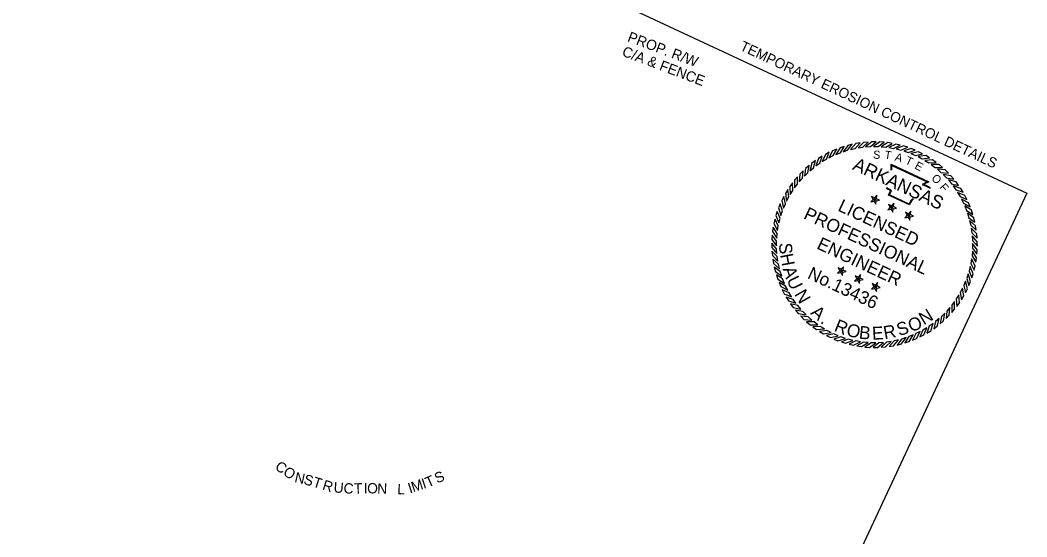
# Model space of a CAD drawing. Extents: x 980231 to 982096, y 1837566 to 1839185.
# Drawn here: x 981512 to 982096, y 1838266 to 1838566 of the extents above; entities that cross this region are included whole.
import ezdxf

# ---------------------------------------------------------------- set-up
doc = ezdxf.new("R2010")
doc.units = 0
for name, color, linetype in [('1', 7, 'Continuous'), ('G-ANNO-SYMB', 7, 'Continuous'), ('G-Border-Sheet', 7, 'Continuous'), ('R_Draft', 7, 'Continuous')]:
    doc.layers.add(name, color=color, linetype=linetype)

msp = doc.modelspace()

# ---------------------------------------------------------------- linework, layer by layer
at = {"layer": 'G-ANNO-SYMB'}
for points in [[(981994.88, 1838494.09), (981992.39, 1838493.47), (981989.67, 1838489.8), (981992.31, 1838490.62)], [(981999.49, 1838494.93), (981996.96, 1838494.51), (981993.96, 1838491.06), (981996.66, 1838491.68)], [(982004.15, 1838495.41), (982001.59, 1838495.19), (981998.33, 1838491.99), (982001.07, 1838492.39)], [(982008.83, 1838495.53), (982006.26, 1838495.51), (982002.76, 1838492.57), (982005.53, 1838492.75)], [(982013.51, 1838495.27), (982010.95, 1838495.46), (982007.23, 1838492.8), (982010, 1838492.77)], [(982018.15, 1838494.65), (982015.61, 1838495.04), (982011.69, 1838492.68), (982014.45, 1838492.43)], [(982022.73, 1838493.67), (982020.23, 1838494.25), (982016.14, 1838492.21), (982018.87, 1838491.74)], [(981981.65, 1838489.43), (981979.37, 1838488.25), (981977.58, 1838484.04), (981979.97, 1838485.46)], [(981985.93, 1838491.33), (981983.57, 1838490.33), (981981.46, 1838486.27), (981983.94, 1838487.5)], [(981990.35, 1838492.88), (981987.92, 1838492.07), (981985.49, 1838488.2), (981988.07, 1838489.23)], [(982027.22, 1838492.33), (982024.77, 1838493.11), (982020.53, 1838491.39), (982023.22, 1838490.71)], [(982031.59, 1838490.64), (982029.21, 1838491.61), (982024.85, 1838490.23), (982027.48, 1838489.34)], [(982035.81, 1838488.62), (982033.52, 1838489.77), (982029.06, 1838488.74), (982031.61, 1838487.65)], [(981973.59, 1838484.66), (981971.53, 1838483.14), (981970.42, 1838478.7), (981972.55, 1838480.48)], [(981977.53, 1838487.2), (981975.35, 1838485.85), (981973.9, 1838481.51), (981976.16, 1838483.12)], [(982039.87, 1838486.27), (982037.67, 1838487.59), (982033.15, 1838486.92), (982035.6, 1838485.63)], [(982043.72, 1838483.6), (982041.64, 1838485.1), (982037.07, 1838484.78), (982039.42, 1838483.3)], [(982047.36, 1838480.65), (982045.39, 1838482.3), (982040.82, 1838482.34), (982043.04, 1838480.69)], [(981966.39, 1838478.69), (981964.58, 1838476.86), (981964.18, 1838472.31), (981966.01, 1838474.39)], [(981969.87, 1838481.82), (981967.93, 1838480.14), (981967.18, 1838475.63), (981969.16, 1838477.56)], [(982050.75, 1838477.42), (982048.92, 1838479.22), (982044.37, 1838479.62), (982046.45, 1838477.79)], [(982053.87, 1838473.93), (982052.2, 1838475.87), (982047.69, 1838476.63), (982049.62, 1838474.64)], [(981960.2, 1838471.66), (981958.7, 1838469.58), (981959.02, 1838465.01), (981960.5, 1838467.36)], [(981963.15, 1838475.3), (981961.5, 1838473.33), (981961.46, 1838468.76), (981963.12, 1838470.99)], [(982056.72, 1838470.21), (982055.2, 1838472.27), (982050.76, 1838473.38), (982052.54, 1838471.25)], [(981957.54, 1838467.81), (981956.21, 1838465.61), (981956.89, 1838461.09), (981958.18, 1838463.54)], [(982008.08, 1838462.01), (982009, 1838462.52), (982009.24, 1838464.49), (982007.89, 1838463.04)], [(982059.26, 1838466.28), (982057.91, 1838468.45), (982053.57, 1838469.91), (982055.17, 1838467.64)], [(982061.49, 1838462.15), (982060.31, 1838464.43), (982056.1, 1838466.22), (982057.52, 1838463.84)], [(981953.16, 1838459.53), (981952.2, 1838457.15), (981953.57, 1838452.79), (981954.46, 1838455.42)], [(981955.19, 1838463.75), (981954.04, 1838461.46), (981955.07, 1838457.01), (981956.16, 1838459.55)], [(982008.08, 1838462.01), (982007.05, 1838462.14), (982005.7, 1838460.69), (982007.64, 1838461.07)], [(982008.08, 1838462.01), (982007.89, 1838463.04), (982006.09, 1838463.87), (982007.05, 1838462.14)], [(982008.08, 1838462.01), (982007.64, 1838461.07), (982008.6, 1838459.34), (982008.85, 1838461.3)], [(982008.08, 1838462.01), (982008.85, 1838461.3), (982010.79, 1838461.68), (982009, 1838462.52)], [(982017.97, 1838457.4), (982017.77, 1838458.43), (982015.98, 1838459.26), (982016.94, 1838457.53)], [(982017.97, 1838457.4), (982018.88, 1838457.91), (982019.12, 1838459.87), (982017.77, 1838458.43)], [(982063.39, 1838457.87), (982062.39, 1838460.23), (982058.33, 1838462.35), (982059.56, 1838459.86)], [(981951.48, 1838455.16), (981950.7, 1838452.71), (981952.41, 1838448.48), (981953.09, 1838451.16)], [(982017.97, 1838457.4), (982016.94, 1838457.53), (982015.59, 1838456.08), (982017.53, 1838456.46)], [(982017.97, 1838457.4), (982017.53, 1838456.46), (982018.49, 1838454.73), (982018.73, 1838456.69)], [(982017.97, 1838457.4), (982018.73, 1838456.69), (982020.68, 1838457.07), (982018.88, 1838457.91)], [(982027.86, 1838452.79), (982026.82, 1838452.92), (982025.47, 1838451.47), (982027.42, 1838451.85)], [(982027.86, 1838452.79), (982027.66, 1838453.82), (982025.86, 1838454.65), (982026.82, 1838452.92)], [(982027.86, 1838452.79), (982027.42, 1838451.85), (982028.38, 1838450.12), (982028.62, 1838452.08)], [(982027.86, 1838452.79), (982028.77, 1838453.3), (982029.01, 1838455.26), (982027.66, 1838453.82)], [(982027.86, 1838452.79), (982028.62, 1838452.08), (982030.57, 1838452.46), (982028.77, 1838453.3)], [(982064.94, 1838453.45), (982064.13, 1838455.89), (982060.26, 1838458.31), (982061.29, 1838455.74)], [(982066.15, 1838448.93), (982065.53, 1838451.42), (982061.85, 1838454.14), (982062.68, 1838451.49)], [(981950.14, 1838450.67), (981949.55, 1838448.17), (981951.59, 1838444.08), (981952.06, 1838446.81)], [(982066.99, 1838444.32), (982066.57, 1838446.85), (982063.12, 1838449.85), (982063.74, 1838447.15)], [(981948.53, 1838441.45), (981948.35, 1838438.89), (981951, 1838435.17), (981951.04, 1838437.94)], [(981949.15, 1838446.09), (981948.77, 1838443.55), (981951.12, 1838439.63), (981951.37, 1838442.4)], [(982067.47, 1838439.66), (982067.25, 1838442.21), (982064.05, 1838445.48), (982064.45, 1838442.73)], [(982067.58, 1838434.97), (982067.57, 1838437.54), (982064.63, 1838441.04), (982064.81, 1838438.28)], [(981948.28, 1838436.77), (981948.3, 1838434.2), (981951.23, 1838430.7), (981951.05, 1838433.47)], [(982067.33, 1838430.3), (982067.51, 1838432.86), (982064.86, 1838436.58), (982064.83, 1838433.81)], [(981948.39, 1838432.09), (981948.61, 1838429.53), (981951.82, 1838426.27), (981951.41, 1838429.01)], [(982066.71, 1838425.65), (982067.09, 1838428.19), (982064.74, 1838432.11), (982064.49, 1838429.35)], [(981948.87, 1838427.43), (981949.29, 1838424.9), (981952.74, 1838421.9), (981952.13, 1838424.6)], [(982065.73, 1838421.07), (982066.31, 1838423.57), (982064.27, 1838427.66), (982063.8, 1838424.93)], [(981949.72, 1838422.82), (981950.33, 1838420.33), (981954.01, 1838417.61), (981953.18, 1838420.26)], [(981950.92, 1838418.29), (981951.73, 1838415.86), (981955.61, 1838413.43), (981954.58, 1838416.01)], [(981988.78, 1838420.61), (981987.74, 1838420.74), (981986.39, 1838419.29), (981988.34, 1838419.67)], [(981988.78, 1838420.61), (981988.58, 1838421.63), (981986.78, 1838422.47), (981987.74, 1838420.74)], [(981988.78, 1838420.61), (981988.34, 1838419.67), (981989.3, 1838417.93), (981989.54, 1838419.9)], [(981988.78, 1838420.61), (981989.69, 1838421.12), (981989.93, 1838423.08), (981988.58, 1838421.63)], [(981988.78, 1838420.61), (981989.54, 1838419.9), (981991.49, 1838420.28), (981989.69, 1838421.12)], [(981998.67, 1838416), (981998.47, 1838417.02), (981996.67, 1838417.86), (981997.63, 1838416.13)], [(981998.67, 1838416), (981999.58, 1838416.51), (981999.82, 1838418.47), (981998.47, 1838417.02)], [(982062.7, 1838412.21), (982063.67, 1838414.59), (982062.29, 1838418.95), (982061.4, 1838416.33)], [(982064.39, 1838416.58), (982065.16, 1838419.03), (982063.45, 1838423.27), (982062.77, 1838420.58)], [(981952.48, 1838413.87), (981953.47, 1838411.51), (981957.53, 1838409.4), (981956.3, 1838411.88)], [(981998.67, 1838416), (981997.63, 1838416.13), (981996.28, 1838414.68), (981998.23, 1838415.06)], [(981998.67, 1838416), (981998.23, 1838415.06), (981999.19, 1838413.32), (981999.43, 1838415.29)], [(981998.67, 1838416), (981999.43, 1838415.29), (982001.37, 1838415.67), (981999.58, 1838416.51)], [(982008.55, 1838411.39), (982008.35, 1838412.41), (982006.56, 1838413.25), (982007.52, 1838411.52)], [(982008.55, 1838411.39), (982009.46, 1838411.9), (982009.7, 1838413.86), (982008.35, 1838412.41)], [(982008.55, 1838411.39), (982009.31, 1838410.68), (982011.26, 1838411.06), (982009.46, 1838411.9)], [(982060.67, 1838407.99), (982061.82, 1838410.28), (982060.8, 1838414.74), (982059.7, 1838412.19)], [(981954.37, 1838409.59), (981955.55, 1838407.31), (981959.76, 1838405.53), (981958.34, 1838407.91)], [(982008.55, 1838411.39), (982007.52, 1838411.52), (982006.17, 1838410.07), (982008.11, 1838410.45)], [(982008.55, 1838411.39), (982008.11, 1838410.45), (982009.07, 1838408.71), (982009.31, 1838410.68)], [(982055.66, 1838400.08), (982057.16, 1838402.17), (982056.84, 1838406.73), (982055.36, 1838404.38)], [(982058.32, 1838403.94), (982059.65, 1838406.13), (982058.98, 1838410.66), (982057.69, 1838408.2)], [(981956.6, 1838405.47), (981957.95, 1838403.29), (981962.29, 1838401.84), (981960.69, 1838404.1)], [(981959.14, 1838401.54), (981960.67, 1838399.47), (981965.1, 1838398.36), (981963.33, 1838400.49)], [(982052.71, 1838396.45), (982054.36, 1838398.41), (982054.4, 1838402.98), (982052.75, 1838400.76)], [(981961.99, 1838397.81), (981963.67, 1838395.87), (981968.18, 1838395.12), (981966.24, 1838397.1)], [(981965.12, 1838394.33), (981966.94, 1838392.52), (981971.5, 1838392.13), (981969.41, 1838393.95)], [(982045.99, 1838389.93), (982047.93, 1838391.61), (982048.68, 1838396.12), (982046.7, 1838394.18)], [(982049.48, 1838393.06), (982051.28, 1838394.88), (982051.68, 1838399.44), (982049.85, 1838397.35)], [(981968.51, 1838391.1), (981970.47, 1838389.44), (981975.04, 1838389.4), (981972.82, 1838391.06)], [(981972.14, 1838388.14), (981974.23, 1838386.65), (981978.79, 1838386.96), (981976.44, 1838388.44)], [(982038.33, 1838384.54), (982040.51, 1838385.9), (982041.96, 1838390.23), (982039.7, 1838388.63)], [(982042.27, 1838387.08), (982044.33, 1838388.61), (982045.44, 1838393.04), (982043.31, 1838391.27)], [(981976, 1838385.48), (981978.19, 1838384.15), (981982.72, 1838384.83), (981980.26, 1838386.12)], [(981980.05, 1838383.13), (981982.34, 1838381.98), (981986.8, 1838383.01), (981984.25, 1838384.1)], [(982025.51, 1838378.86), (982027.95, 1838379.67), (982030.37, 1838383.55), (982027.8, 1838382.52)], [(982029.93, 1838380.42), (982032.29, 1838381.41), (982034.41, 1838385.47), (982031.92, 1838384.24)], [(982034.21, 1838382.31), (982036.49, 1838383.49), (982038.28, 1838387.7), (982035.9, 1838386.28)], [(981984.27, 1838381.1), (981986.65, 1838380.14), (981991.01, 1838381.51), (981988.39, 1838382.4)], [(981988.64, 1838379.42), (981991.09, 1838378.64), (981995.33, 1838380.35), (981992.64, 1838381.03)], [(981993.13, 1838378.08), (981995.63, 1838377.49), (981999.72, 1838379.54), (981996.99, 1838380)], [(981997.71, 1838377.09), (982000.25, 1838376.71), (982004.17, 1838379.06), (982001.41, 1838379.32)], [(982002.36, 1838376.47), (982004.92, 1838376.29), (982008.64, 1838378.94), (982005.87, 1838378.98)], [(982007.03, 1838376.22), (982009.6, 1838376.24), (982013.1, 1838379.18), (982010.34, 1838378.99)], [(982011.72, 1838376.33), (982014.27, 1838376.55), (982017.53, 1838379.76), (982014.79, 1838379.36)], [(982016.38, 1838376.81), (982018.91, 1838377.23), (982021.91, 1838380.68), (982019.21, 1838380.07)], [(982020.98, 1838377.66), (982023.47, 1838378.27), (982026.19, 1838381.95), (982023.55, 1838381.12)]]:
    msp.add_lwpolyline(points, close=True, dxfattribs=at)
for points in [[(982017.57, 1838479.15), (982017.58, 1838482.47), (982039.4, 1838472.32), (982036.51, 1838470.88), (982038, 1838470.2), (982039.24, 1838469.64), (982040.42, 1838468.93)], [(982017.95, 1838479.15), (982017.96, 1838481.88), (982038.52, 1838472.3), (982035.62, 1838470.86), (982037.84, 1838469.86), (982039.06, 1838469.3), (982040.22, 1838468.61)], [(982030.42, 1838462.04), (982029.91, 1838461.91), (982029.57, 1838461.51), (982028.92, 1838460.44), (982028.22, 1838458.93), (982016.04, 1838464.61), (982016.99, 1838466.64), (982017.2, 1838467.1), (982016.78, 1838467.48), (982015.05, 1838468.28), (982014.96, 1838468.9)], [(982030.33, 1838462.41), (982029.69, 1838462.25), (982029.26, 1838461.74), (982028.58, 1838460.62), (982028.03, 1838459.44), (982016.55, 1838464.79), (982017.34, 1838466.48), (982017.67, 1838467.19), (982016.99, 1838467.8), (982015.4, 1838468.54), (982015.34, 1838468.95)]]:
    msp.add_lwpolyline(points, dxfattribs=at)
at = {"layer": 'G-Border-Sheet'}
msp.add_lwpolyline([(980671.38, 1839184.86), (981846.87, 1838636.72), (981825.93, 1838591.82), (982096.33, 1838465.73), (981897.02, 1838038.3), (981897.02, 1838038.3), (981919.96, 1838087.51), (981609.41, 1838232.32), (981586.46, 1838183.11), (980846.18, 1838528.31), (980876.72, 1838593.79), (980491.54, 1838773.4), (980461.01, 1838707.92), (980451.13, 1838712.53)], close=True, dxfattribs=at)
msp.add_lwpolyline([(980671.38, 1839184.86), (981846.87, 1838636.72), (981825.93, 1838591.82), (982096.33, 1838465.73), (981897.02, 1838038.3), (981897.02, 1838038.3), (981919.96, 1838087.51), (981609.41, 1838232.32), (981586.46, 1838183.11), (980846.18, 1838528.31), (980876.72, 1838593.79), (980491.54, 1838773.4), (980461.01, 1838707.92), (980451.13, 1838712.53)], close=True, dxfattribs=at)
msp.add_lwpolyline([(980671.38, 1839184.86), (981846.87, 1838636.72), (981825.93, 1838591.82), (982096.33, 1838465.73), (981897.02, 1838038.3), (981897.02, 1838038.3), (981919.96, 1838087.51), (981609.41, 1838232.32), (981586.46, 1838183.11), (980846.18, 1838528.31), (980876.72, 1838593.79), (980491.54, 1838773.4), (980461.01, 1838707.92), (980451.13, 1838712.53)], close=True, dxfattribs=at)
msp.add_lwpolyline([(980671.38, 1839184.86), (981846.87, 1838636.72), (981825.93, 1838591.82), (982096.33, 1838465.73), (981897.02, 1838038.3), (981897.02, 1838038.3), (981919.96, 1838087.51), (981609.41, 1838232.32), (981586.46, 1838183.11), (980846.18, 1838528.31), (980876.72, 1838593.79), (980491.54, 1838773.4), (980461.01, 1838707.92), (980451.13, 1838712.53)], close=True, dxfattribs=at)

# ---------------------------------------------------------------- texts
at = {"layer": '1'}
msp.add_text('TEMPORARY EROSION CONTROL DETAILS', height=5.8625, rotation=335, dxfattribs=at).set_placement((981929.3, 1838548.99))
at = {"layer": 'G-ANNO-SYMB'}
for s, height, rotation, p in [('S', 4.75, 354.77256, (982006.88, 1838485.88)), ('T', 4.75, 351.90148, (982013.49, 1838485.79)), ('A', 4.75, 343.67877, (982019.35, 1838484.72)), ('ARKANSAS', 7.747, 335, (981994.58, 1838479.7)), ('T', 4.75, 336.47887, (982025.31, 1838482.98)), ('E', 4.75, 331.67203, (982030.75, 1838480.28)), ('O', 4.75, 316.2218, (982040.51, 1838473.94)), ('F', 4.75, 310.36282, (982045.25, 1838468.97)), ('LICENSED', 7.5, 335, (981986.08, 1838455.77)), ('PROFESSIONAL', 7.5, 335, (981966.21, 1838451.19)), ('S', 7.5, 273.16364, (981952.45, 1838436.81)), ('ENGINEER', 7.5, 335, (981973.86, 1838433.78)), ('H', 7.5, 280.61905, (981953.06, 1838430.04)), ('A', 7.5, 288.44722, (981954.49, 1838421.82)), ('U', 7.5, 295.90262, (981956.66, 1838415.41)), ('No.13436', 7.47, 335, (981968.45, 1838416.58)), ('N', 7.5, 299.93262, (981961.15, 1838407.16)), ('A', 7.5, 318.09908, (981970.28, 1838395.8)), ('N', 7.5, 31.10067, (982036.52, 1838388.96)), ('.', 7.5, 326.30002, (981976.03, 1838390.7)), ('R', 7.5, 338.22866, (981983.97, 1838385.96)), ('O', 7.5, 346.42961, (981991.13, 1838383.15)), ('B', 7.5, 353.88501, (981998.61, 1838381.42)), ('E', 7.5, 2.83149, (982006.62, 1838380.67)), ('R', 7.5, 10.65967, (982013.77, 1838381)), ('S', 7.5, 18.48784, (982022.18, 1838382.71)), ('O', 7.5, 19.77573, (982028.95, 1838385.04))]:
    msp.add_text(s, height=height, rotation=rotation, dxfattribs=at).set_placement(p)
at = {"layer": 'R_Draft'}
for s, rotation, p in [('PROP. R/W', 339.24286, (981864.08, 1838554.02)), ('C/A & FENCE', 339.24286, (981860.89, 1838545.6)), ('C', 325.79949, (981659.43, 1838305.89)), ('O', 325.79949, (981664.12, 1838302.7)), ('N', 347.51573, (981670.91, 1838298.2)), ('S', 344.72278, (981676.14, 1838297.04)), ('T', 342.75684, (981681.41, 1838295.61)), ('T', 23.89132, (981748.71, 1838294.87)), ('S', 23.89132, (981754.06, 1838297.25)), ('R', 342.75684, (981687, 1838293.87)), ('U', 355.24928, (981693.75, 1838292.21)), ('C', 355.24928, (981699.5, 1838291.73)), ('T', 1.19466, (981705.77, 1838291.45)), ('I', 358.3997, (981711.34, 1838291.71)), ('O', 358.3997, (981713.32, 1838291.65)), ('N', 358.3997, (981719.18, 1838291.49)), ('L', 358.00585, (981730.8, 1838291.12)), ('I', 18.08089, (981738.2, 1838291.57)), ('M', 18.08089, (981740.09, 1838292.19)), ('I', 18.08089, (981746.2, 1838294.18))]:
    msp.add_text(s, height=6, rotation=rotation, dxfattribs=at).set_placement(p)

doc.saveas('drawing.dxf')
